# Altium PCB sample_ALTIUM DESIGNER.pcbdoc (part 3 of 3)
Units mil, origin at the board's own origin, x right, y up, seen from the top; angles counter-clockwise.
Board outline 2485.01 x 1905 mil, 6 copper layers (1 TallParts (2oz), 2 RTNS (2oz), 3 InternalPlane1 (2 oz), 4 InternalPlane2 (2 oz), 5 Signal (2oz), 6 LoParts (2oz)), stack 46.8 mil thick; 176 components, 89 nets, 769 pads, 0 vias.
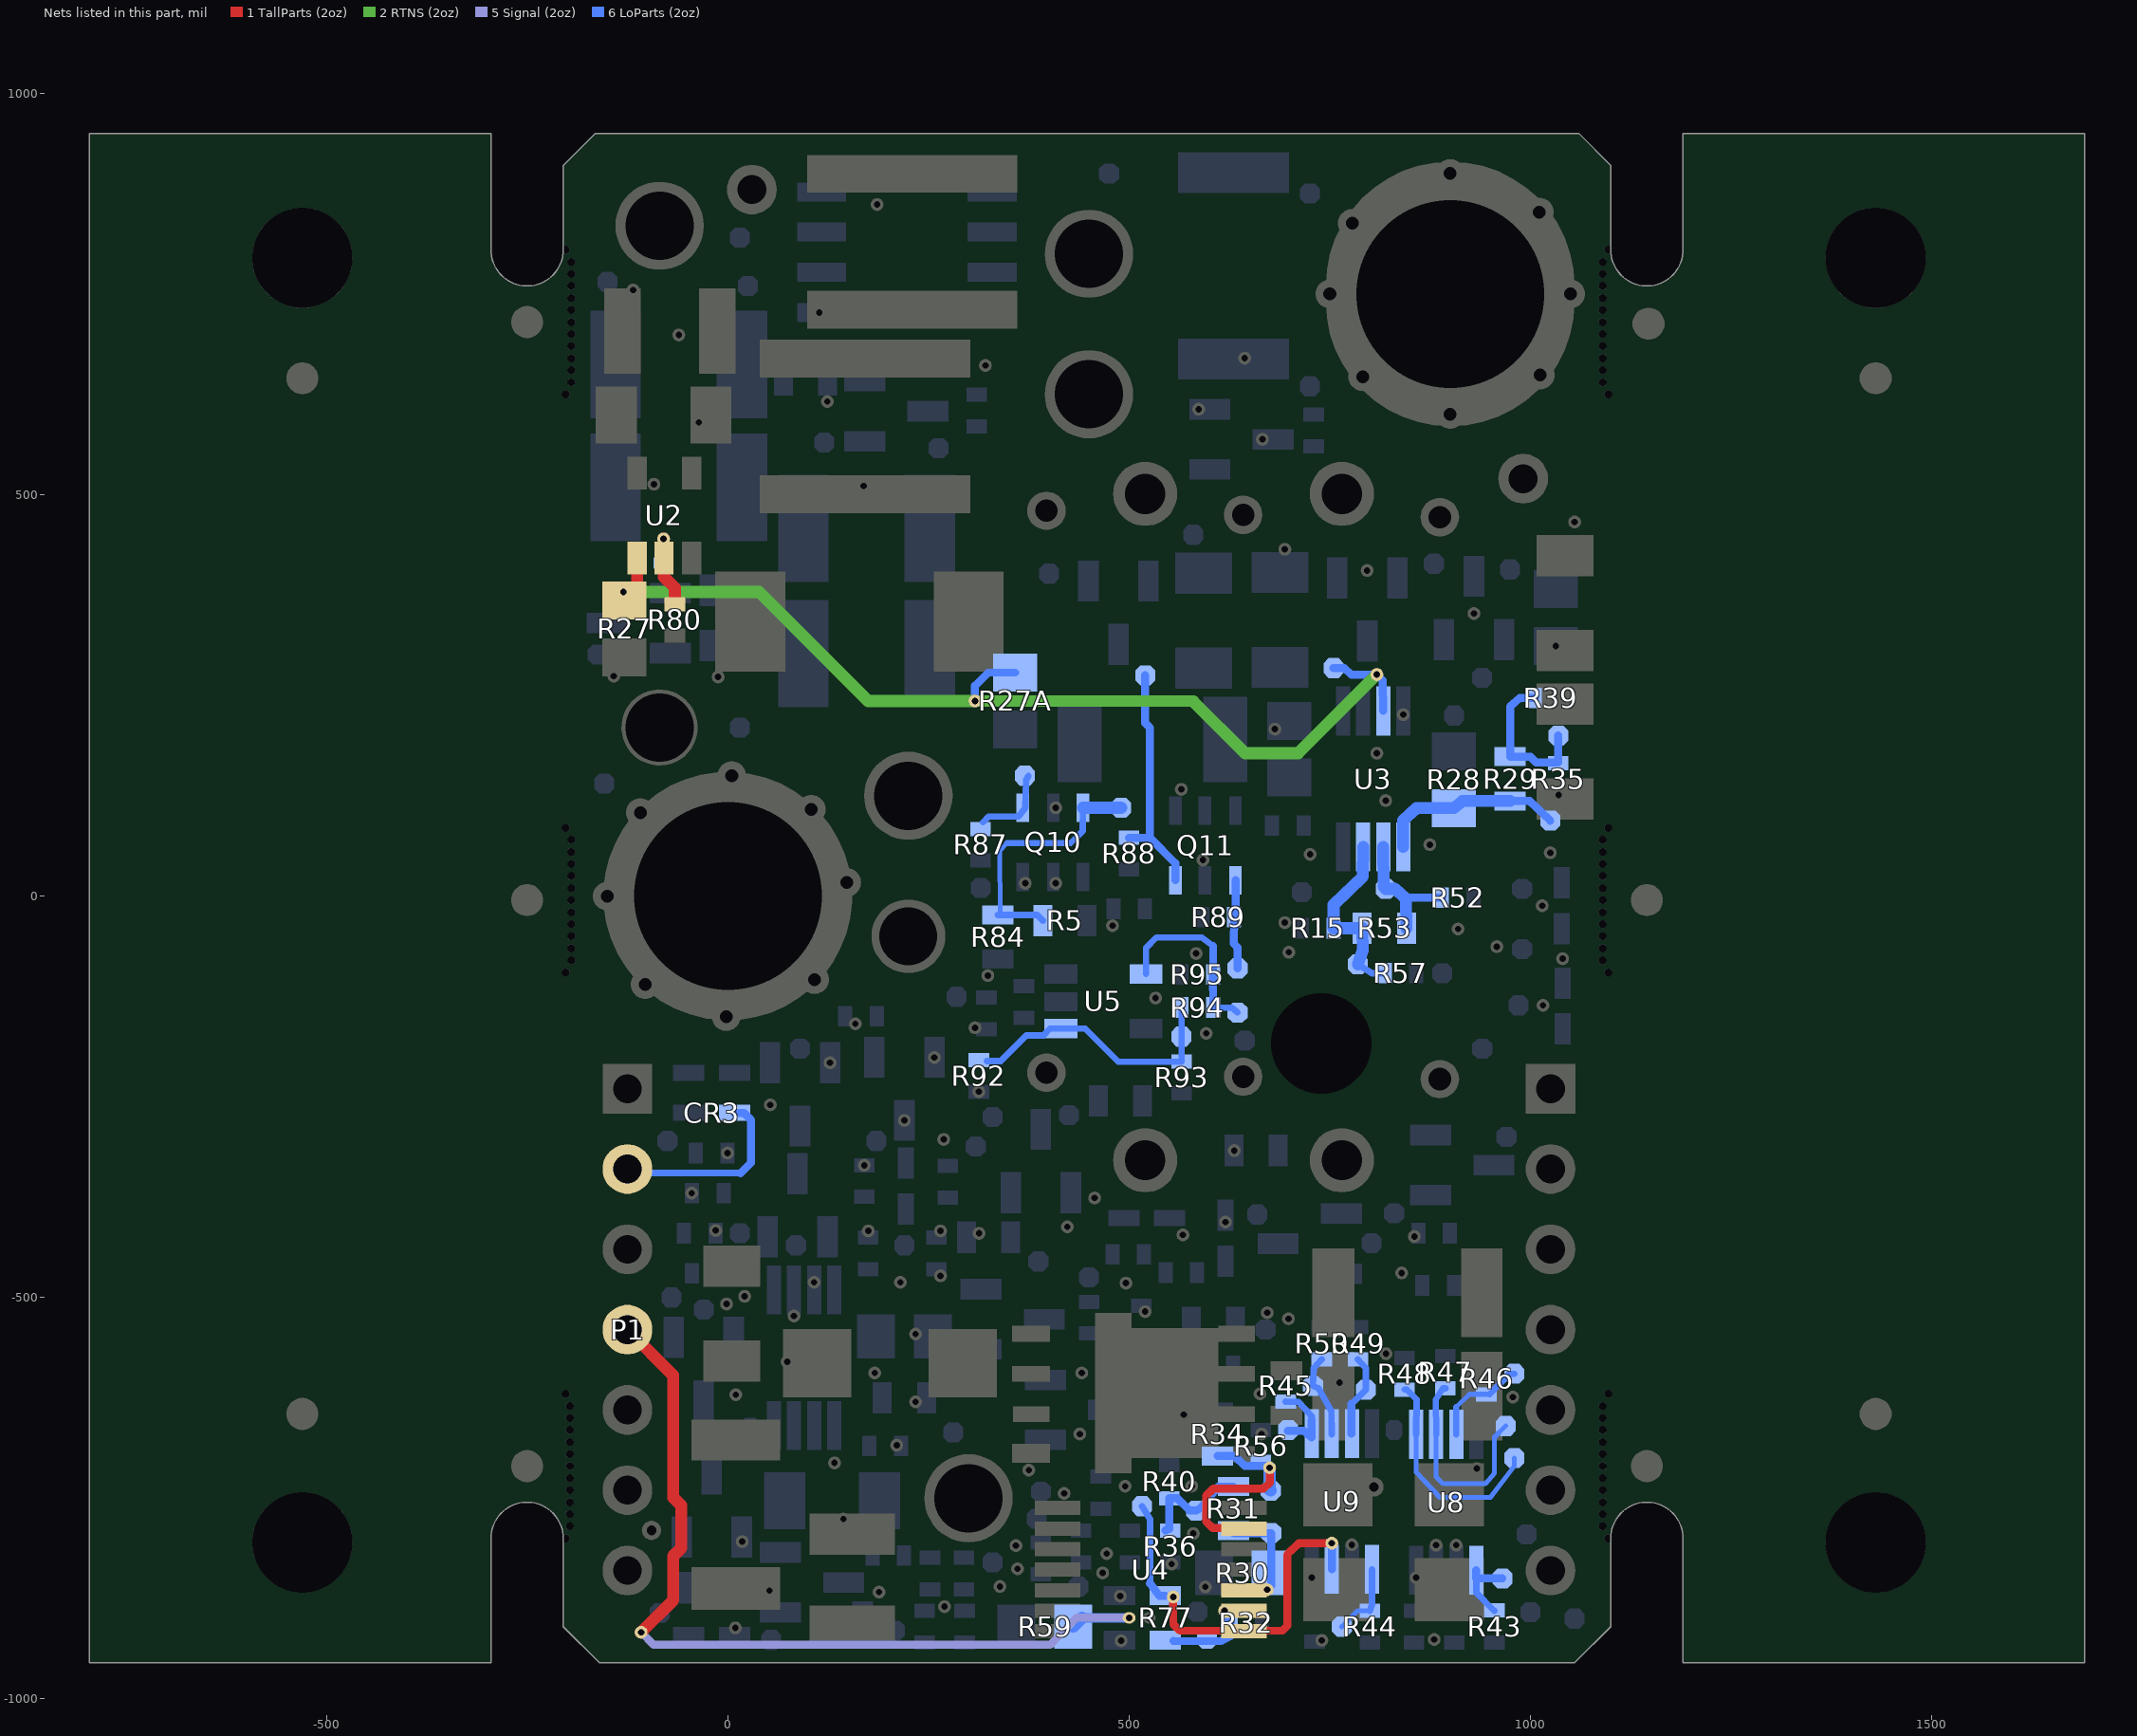
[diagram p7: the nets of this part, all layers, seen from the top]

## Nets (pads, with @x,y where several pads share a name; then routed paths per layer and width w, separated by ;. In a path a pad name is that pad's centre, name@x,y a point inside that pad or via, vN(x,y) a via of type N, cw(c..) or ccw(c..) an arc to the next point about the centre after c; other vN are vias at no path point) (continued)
NetQ10_4: pad.8@370,150 Q10.4 R87.2 | length 101.7
  6 LoParts (2oz) w8: R87.2@317.87,92 324.87,99 362,99 368.48,107.28 369.57,108.69 Q10.4@370.6,110 ; Q10.4@370.6,110.01 370.6,110.22 371.6,144 373.68,148.16 pad.8@374.6,150
NetQ10_6: pad.8@490,110 Q10.6 R5.1 R84.2 | length 332.3
  6 LoParts (2oz) w6: R84.2@339.5,-23.5 339.5,-23.44 339,57 348,66
  6 LoParts (2oz) w8: R84.2@336.54,-23.43 339.5,-23.44 385.5,-23.5 R5.1@392.45,-30.54 ; 348,66 427.1,66 442.1,81 442.5,110 Q10.6@442.5,110.31 Q10.6@445.6,110
  6 LoParts (2oz) w15: Q10.6@442.5,110 445.6,110 pad.8@490,110
NetQ11_4: pad.8@635,-90 Q11.4 R89.2 | length 111.7
  6 LoParts (2oz) w10: Q11.4@632.5,19.69 632.5,-17.5 R89.2@630.69,-26 630.5,-59.5 635,-64 pad.8@635,-90
NetQ11_6: pad.8@520,275 Q11.6 R88.2 | length 297.1
  6 LoParts (2oz) w10: R88.2@499.6,72.69 525.82,72.69 ; pad.8@520,275 520,215.5 525.82,209.69 525.82,72.69 ; Q11.6@557.5,19.69 557.5,41 525.82,72.69
NetR15_1: pad.8@785,-85 R15.1 R53.2 R57.1 U3.7 | length 235
  6 LoParts (2oz) w8: pad.8@785,-85 802.5,-96 R57.1@818.32,-96
  6 LoParts (2oz) w15: pad.8@785,-85 791,-68 R53.2@790.44,-40 R15.1@754.69,-40 754.69,-10.93 791.11,24.5 U3.7@791.5,61.35
NetR27_2: pad.2@308,243 pad.2@808.61,276 pad.2@-130,378.87 pad.8@754.61,284 R27.2 R27A.2 U2.1 U3.3 | length 1303.3
  1 TallParts (2oz) w15: pad.2@-130,378.87 -128.78,378.84 -113,378.5 U2.1@-113,421
  2 RTNS (2oz) w15: pad.2@-130,378.87 39,378.87 174.87,243 pad.2@308,243 308,243.24 580,242.5 644.5,178 710.61,178 pad.2@808.61,276
  6 LoParts (2oz) w10: pad.2@308,243 308,262 324.43,278.43 R27A.2@358,278.43 ; pad.8@754.61,284 768,284 777,276 pad.2@808.61,276 816.11,268.5 U3.3@816.5,230.65
NetR28_2: pad.8@1024.61,94 R28.2 R29.2 U3.5 | length 235.3
  6 LoParts (2oz) w10: R29.2@974.61,118.44 999,118.5 pad.8@1024.61,94
  6 LoParts (2oz) w15: U3.5@841.12,61.35 841.11,94.5 858,109.5 R28.2@904.33,109.56 915.5,118.5 R29.2@974.61,118.44
NetR29_1: pad.8@1034.61,200 R29.1 R35.1 R39.2 | length 193.6
  6 LoParts (2oz) w10: R39.2@1005.32,247 986.61,247 974.61,236 R29.1@974.61,173.56 1000,173.5 1007,166.5 1034.6,166.69 pad.8@1034.61,200
NetR30_2: pad.2@672.01,-864 pad.8@677,-793.5 R30.2 R31.2 U4.3 | length 136.4
  6 LoParts (2oz) w10: R31.2@629.28,-793 631,-793.5 pad.8@677,-793.5 677.01,-843 R30.2@677.01,-859 ; pad.2@672.01,-864 R30.2@677.01,-859 ; R30.2@676.43,-843 R30.2@677.01,-859
NetR31_1: pad.8@583.5,-765.5 R31.1 R36.1 R40.2 | length 150.9
  6 LoParts (2oz) w10: R36.1@545,-790.31 549.12,-788.41 549.94,-788.03 550,-788 R40.2@550.01,-750 550.01,-749.69 560,-750 574.51,-764.5 575.01,-765 pad.8@583.5,-765.5 pad.8@590,-761.5 ; pad.8@583.73,-765.15 pad.8@590,-761.5 ; R31.1@630,-735.44 611,-735.5 pad.8@590,-761.5
NetR32_2: pad.2@619,-890 pad.8@597,-925 R32.2 R77.1 U4.2 | length 133.5
  1 TallParts (2oz) w10: pad.2@619,-890 U4.2@643.12,-889.41
  6 LoParts (2oz) w6: pad.2@619,-890 pad.2@622.01,-890
  6 LoParts (2oz) w10: R77.1@555.01,-927.56 559,-928 597,-928 614,-928 626,-922 R32.2@626.32,-905 ; pad.2@619,-890 R32.2@626.24,-904.87 ; R32.2@626.24,-904.87 626.32,-904.87 R32.2@626.32,-905 ; R32.2@626.24,-904.87 R32.2@626.32,-905
NetR34_2: pad.2@675,-712 pad.8@676.5,-740.5 R34.2 R56.1 U4.6 | length 280.9
  1 TallParts (2oz) w10: U4.6@643.14,-787.05 604.06,-787.05 596.01,-779 596.01,-747 605.01,-738 667.51,-738 675,-731 pad.2@675,-712
  6 LoParts (2oz) w10: R34.2@610.01,-697.56 631,-697.5 644.01,-709.69 664,-709.69 R56.1@670.01,-709.69
  6 LoParts (2oz) w15: pad.2@675,-712 675,-739 pad.8@676.5,-740.5
NetR43_2: pad.8@965,-850 R43.2 U8.1 | length 92.5
  6 LoParts (2oz) w8: U8.1@932.5,-850 932.51,-867.81 954.61,-889.91 R43.2@955.01,-890.31
  6 LoParts (2oz) w10: U8.1@932.51,-839.65 932.5,-850 pad.8@965,-850
NetR44_2: pad.8@765.01,-910 R44.2 U9.1 | length 95.2
  6 LoParts (2oz) w6: pad.8@765.01,-910 784.7,-890.31 R44.2@800.01,-890.31
  6 LoParts (2oz) w8: R44.2@800.01,-890.31 802.51,-882.81 U9.1@802.5,-838.65
NetR45_1: pad.8@698,-665 R45.1 U9.5 | length 100.2
  6 LoParts (2oz) w8: R45.1@695.03,-629.87 R45.1@695.01,-629.69 711,-630 727.5,-648 U9.5@727.51,-652.19
  6 LoParts (2oz) w10: pad.8@697.5,-666 698,-666 717.5,-666 724.96,-672.34 727.5,-674.5 U9.5@727.5,-669.35 ; U9.5@727.5,-669.35 U9.5@727.51,-652.19
NetR46_1: pad.8@980,-595 R46.1 U8.7 | length 123.5
  6 LoParts (2oz) w6: 907.5,-636.5 924,-620.5 R46.1@944.95,-620.49 ; R46.1@945.01,-620.69 R46.1@949,-620.5
  6 LoParts (2oz) w8: U8.7@907.51,-670.35 907.5,-636.5 ; R46.1@949,-620.5 962,-607 974,-595 pad.8@980,-595
NetR47_1: pad.8@969,-660 R47.1 U8.6 | length 262.9
  6 LoParts (2oz) w6: U8.6@882.51,-670.35 882.5,-723 891,-732 944,-732 955,-719 955,-674 pad.8@969,-660
  6 LoParts (2oz) w8: U8.6@882.51,-670.35 882,-627 891,-613 R47.1@894,-613
NetR48_1: pad.8@980,-700 R48.1 U8.5 | length 275.8
  6 LoParts (2oz) w6: U8.5@857.51,-670.35 857.51,-717.5 887,-749 950,-749 980,-710 pad.8@980,-700
  6 LoParts (2oz) w8: R48.1@843,-614.69 846,-615 858,-627 U8.5@857.51,-670.35
NetR49_1: pad.8@795,-615 R49.1 U9.7 | length 113.8
  6 LoParts (2oz) w8: U9.7@777,-642 777,-632.5 pad.8@795,-615 795,-588 R49.1@785,-577
  6 LoParts (2oz) w10: U9.7@777,-669.85 777,-669.35 777.03,-669.23 777,-632.5
NetR50_1: pad.8@729,-610 R50.1 U9.6 | length 106.1
  6 LoParts (2oz) w8: R50.1@740,-577 730,-588 pad.8@729,-610 736,-613 752,-641 U9.6@752.5,-669.35 U9.6@752.51,-670.35
NetR52_2: pad.8@819.61,9 R52.2 R53.1 U3.6 | length 164
  6 LoParts (2oz) w10: 846,-2 R52.2@889.61,-2
  6 LoParts (2oz) w15: U3.6@816.5,61.35 817,12 819.72,9.5 pad.8@819.61,9 831,9 845,-3 R53.1@845.56,-40
NetR77_2: pad.2@555,-873 pad.2@752.5,-806 pad.8@516,-760 R77.2 U4.1 U9.3 | length 490.2
  1 TallParts (2oz) w10: pad.2@555,-873 555.01,-907 563.01,-915 643.14,-915 691.01,-915 697.01,-909 697.01,-820 711.5,-806 pad.2@752.5,-806
  6 LoParts (2oz) w8: pad.8@516,-760 526,-776 526,-856
  6 LoParts (2oz) w10: 526,-856 537.44,-871.44 R77.2@545,-871.44 ; U9.3@752.5,-838.65 pad.2@752.5,-806
NetR80_2: pad.2@-80,445 pad.8@-80,415 R80.2 U2.2 | length 116.9
  1 TallParts (2oz) w15: pad.2@-80,445 U2.2@-79.5,421 -79.5,397.5 -66,384 R80.2@-66,363.69
  6 LoParts (2oz) w10: pad.8@-80,415 pad.2@-80,445
NetR92_1: pad.8@565.27,-175 R92.1 R93.2 R94.2 U5.1 | length 343.9
  6 LoParts (2oz) w8: R92.1@322.73,-205.32 340.18,-205.32 372,-173.5 393,-173.5 401.5,-165 U5.1@415,-165 445,-165 486.31,-206.31 R93.2@565.27,-206.31 pad.8@565.27,-175 R94.2@565.31,-138.73
NetR94_1: pad.8@635,-145 R94.1 R95.1 U5.4 | length 234.1
  6 LoParts (2oz) w8: U5.4@521,-97 521,-65 534,-51.5 590.5,-51.5 604.68,-62.18 ; R94.1@604.68,-138.73 628,-139 pad.8@635,-145
  6 LoParts (2oz) w10: R95.1@604.18,-97.74 R94.1@604.68,-138.73 ; R95.1@604.68,-97.73 604.68,-62.18
PWM: CR3.2 P1.2 | length 238.7
  6 LoParts (2oz) w8: P1.2@-119.99,-345 16.01,-345
  6 LoParts (2oz) w10: P1.2@-124.99,-340 P1.2@-119.99,-345 ; CR3.2@8.51,-270 20.01,-270 29.01,-279 29.01,-332 16.01,-345
SLOWTRIPSET: P1.4 pad.2@500,-899 pad.2@-108,-917 R59.1 | length 1132.2
  1 TallParts (2oz) w15: P1.4@-124.99,-540 -68,-596.99 -68,-749 -58,-759 -58,-812 -68,-822 -68,-877 pad.2@-108,-917
  5 Signal (2oz) w10: pad.2@-108,-917 -92.5,-932.5 401.68,-932.5 434.01,-899 pad.2@500,-899 pad.2@502.01,-899
  6 LoParts (2oz) w12: R59.1@441.45,-899 pad.2@500,-899 pad.2@502.01,-899
  6 LoParts (2oz) w15: R59.1@430.45,-910 R59.1@441.45,-899
pads on no net: CR14.2 CR15.2 CR16.2 CR23.2 CR25.2 CR29.2 FD1.FD? FD2.FD? FD3.FD? FD4.FD5 FD5.FD? FD6.FD? FD7.FD? FD8.FD6 FD9.FD? FD10.FD? P3.1 P4.1 U10.1 U10.4 U10.6 U10.7

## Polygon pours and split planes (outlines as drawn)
28VA on 1 TallParts (2oz) (solid): 957.5,372.5 935,394.5 812,557 426,558 426,557 184,203 184.01,-53 225.01,-94 300.01,-94 326,-68 333,-59 644.5,-59.5 809,-59 958.5,234.5 957.01,200
28VOUTPUT on 1 TallParts (2oz) (solid): 1057.99,881 1026.99,912 383,911 382,854 383,685 338,685 337,578.5 337,563 361,534.5 431,535 503,576 1057,576.5
28VBUS on 1 TallParts (2oz) (solid): -11.95,164.71 -106.95,124.71 -143.95,124.71 -162.95,104.71 -162.95,-285.29 -110,-285 72.1,-469.14 115.1,-511.14 703.03,-510.54 798,-405 834.5,-372.5 836,-297 789.82,-238.43 644,-185 642,-133 485,-133 431.5,-100 277,-100.5 246,-122 209.5,-122 173,-103.5 158.5,-83 153.5,-56 155.05,-21.29 155.86,83.9 75.05,164.71 50.05,164.71
28VOUTPUT on 5 Signal (2oz) (solid): 968,521 1069,420 1069,-286 980,-286 905,-284 906,-179 904,495 924,515 972,515
28VOUTPUT on 3 InternalPlane1 (2 oz) (split plane): 1200.02,-799.96 ccw(c1145,-799.96) 1101.03,-766.9 1101.03,771.97 ccw(c1145,805.04) 1200.02,805.04 1200.02,939.99 1680,939.99 1679.99,-944.99 1200.02,-944.99
28VOUTPUT on 3 InternalPlane1 (2 oz) (split plane): 329.15,420.01 423.85,420.01 445.05,441.21 446.49,536.65 cw(c456.5,536.5) 449.42,543.58 473.92,568.08 cw(c481,561) 481,571.01 564,571.01 cw(c564,561) 571.26,567.9 590.26,547.9 cw(c583,541) 593.02,541 593.02,441.92 608.42,430.01 650.85,430.01 657.92,437.08 ccw(c665,430) 657.84,437 657.82,436.98 657.84,437 657.87,437.04 689.99,470.07 689.99,519.5 cw(c700,519.5) 692.96,526.63 732.96,566.13 cw(c740,559) 740,569.01 794,569.01 cw(c794,559) 800.88,566.27 800.86,566.29 800.88,566.27 834.84,534.31 cw(c828,527) 838.02,527 838.02,466.15 874.15,430.01 956.27,430.01 cw(c966.29,430) 960.02,437.81 1081,534.81 1081,711.67 cw(c900,750) 1046.92,637.55 cw(c1038.97,643.63) 1031.01,649.72 ccw(c900,750) 1064.99,750 ccw(c900,750) 1064.72,759.28 cw(c1074.72,759.85) 1081,767.65 1081,895.04 cw(c1091.02,895.04) 1089.99,905 1089.99,905.87 1055.88,939.99 389.19,939.99 cw(c380,936.01) 390.02,936.01 cw(c380,936.01) 387.12,928.97 300.02,840.88 300.02,449.15
no net on 3 InternalPlane1 (2 oz) (split plane): -181,154.91 ccw(c-191.01,155) -181,155 -181,895.46 ccw(c-191.01,895.46) -194.97,904.66 -194.97,905.85 -160.84,939.99 369.84,939.99 282.88,852.04 ccw(c290,845) 279.99,845 279.99,445 ccw(c290,445) 282.92,437.92 317.92,402.92 ccw(c325,410) 325,399.99 355.82,399.99 235.85,280.01 65,280.01 ccw(c65,270) 54.99,270 54.99,186.01 -23,186.01 ccw(c-23,176) -31.61,181.12 ccw(c1.97,-0.83) -102.74,151.71 ccw(c-97.07,143.45) -106.48,140.01
28VA on 3 InternalPlane1 (2 oz) (split plane): 186.92,-117.74 158.52,-110.22 158.52,-83.56 ccw(c-0.83,-1.97) 177.79,-13.92 182.04,-0.87 ccw(c179,6) 186.39,4.66 188.39,15.66 ccw(c181,17) 188.52,17 ccw(c181,17) 188.39,18.34 182.39,51.34 ccw(c175,50) 181.29,54.11 102.91,174.55 ccw(c93,176) 103.02,176 ccw(c93,176) 93,186.01 75.02,186.01 75.02,259.99 240,259.99 ccw(c240,270) 247.08,262.92 384.15,399.99 428,399.99 ccw(c428,410) 435.08,402.92 462.08,429.92 ccw(c455,437) 465.01,436.85 466.45,532.29 485.15,550.99 559.7,550.99 572.99,537 572.99,437 ccw(c583,437) 576.9,429.06 576.88,429.08 576.9,429.06 598.85,412.09 ccw(c605,420) 605,409.99 655,409.99 ccw(c655,420) 662.08,412.92 672.08,422.92 ccw(c665,430) 672.2,423.04 707.16,459 ccw(c700,466) 710.02,466 710.02,515.31 744.11,548.99 790.03,548.99 817.99,522.67 817.99,462 ccw(c828,462) 820.92,454.92 862.92,412.92 ccw(c870,420) 870,409.99 956.27,409.99 956.27,191.29 ccw(c966.29,191.29) 956.27,191.12 956.99,146.92 956.99,146.84 956.99,147 956.99,81.05 901.77,24.03 641.06,25.01 641.04,25.01 641.06,25.01 ccw(c641,15) 635.3,23.23 624.87,16.01 459,16.01 ccw(c459,6) 451.92,13.08 422.92,-15.92 ccw(c430,-23) 419.99,-23.08 419.99,-23.06 419.99,-23.08 420.54,-115.35 269.02,-114.99 ccw(c269,-125) 265.9,-115.48 222.9,-129.48 ccw(c226,-139) 222.16,-129.75 187.45,-117.89 ccw(c185,-125)
28VBUS on 3 InternalPlane1 (2 oz) (split plane): -181,-279.99 -95,-279.99 cw(c-95,-290) -87.92,-282.92 67.08,-437.92 cw(c60,-445) 70.02,-445 70.02,-465.85 104.15,-499.99 489.69,-499.99 514.02,-481.97 cw(c520,-490) 520,-479.99 710,-479.99 cw(c710,-490) 717.08,-482.92 739.15,-504.99 860.85,-504.99 889.99,-475.85 889.99,-298.07 830.08,-254.08 830.07,-254.07 830.08,-254.08 cw(c836,-246) 825.99,-246 825.99,-176.15 762.85,-113.01 620.15,-113.01 556.08,-177.08 cw(c549,-170) 549,-180.01 475,-180.01 cw(c475,-170) 467.9,-177.06 426.44,-135.39 270.58,-135.02 229.1,-148.52 cw(c226,-139) 217.31,-143.97 182.82,-132.2 149.08,-123.26 cw(c151,-116) 143.49,-116 143.49,-80 cw(c151,-80) 147.96,-73.13 170.13,-5.04 ccw(c-0.83,-1.97) 170.16,-1.97 ccw(c-0.83,-1.97) 156.91,64.01 90.55,165.99 69.36,165.99 cw(c65,175) 60.64,165.99 16.22,165.99 cw(c10.19,173.98) 9.72,163.98 ccw(c1.97,-0.83) -47.18,156.67 -93.54,130.63 cw(c-96,135) -96,129.99 -181,129.99 -181,36.17 cw(c0.83,1.97) -176.88,53.44 cw(c-167.26,50.66) -157.25,50.66 cw(c-167.26,50.66) -157.64,47.87 ccw(c0.83,1.97) -155.68,-50.23 cw(c-165.18,-53.39) -155.17,-53.39 cw(c-165.18,-53.39) -174.69,-56.56 cw(c0.83,1.97) -181,-32.23
no net on 3 InternalPlane1 (2 oz) (split plane): -155.84,-944.99 -183.86,-916.97 ccw(c-191.01,-909.96) -181,-909.96 -181,-300.01 -99.15,-300.01 49.99,-449.15 49.99,-470 ccw(c60,-470) 52.92,-477.08 92.92,-517.08 ccw(c100,-510) 100,-520.01 493,-520.01 ccw(c493,-510) 498.98,-518.03 523.31,-500.01 705.85,-500.01 727.92,-522.08 ccw(c735,-515) 735,-525.01 865,-525.01 ccw(c865,-515) 872.08,-522.08 907.08,-487.08 ccw(c900,-480) 910.02,-480 910.02,-293 ccw(c900,-293) 905.92,-284.92 905.93,-284.93 905.92,-284.92 846.02,-240.93 846.02,-172 ccw(c836,-172) 843.08,-164.92 774.08,-95.92 ccw(c767,-103) 767,-92.99 616,-92.99 ccw(c616,-103) 608.92,-95.92 544.85,-159.99 479.16,-159.99 440.61,-121.23 440.04,-27.12 463.15,-4.01 628,-4.01 ccw(c628,6) 633.7,-2.23 644.11,4.97 905.94,3.99 ccw(c906,14) 913.2,7.03 913.2,7.04 974.19,70.03 ccw(c967,77) 974.2,70.04 974.2,70.03 ccw(c967,77) 977.02,77 977.02,147 ccw(c967,147) 977.01,147.16 976.3,191.37 976.3,191.45 976.3,191.29 976.3,425.19 1081,509.13 1081,-909.96 ccw(c1091.02,-909.96) 1081.85,-914 1050.86,-944.99
28VOUTPUT on 3 InternalPlane1 (2 oz) (split plane): -784.98,-944.95 -784.98,939.99 -305.01,939.99 -305.01,805.04 ccw(c-250,805.04) -201.03,779.97 -201.03,155 cw(c-191.01,155) -201.03,155.09 -201.03,155.04 -205.01,-289.91 ccw(c-195,-290) -201.03,-298 -201.03,-774.89 ccw(c-250,-799.96) -305.01,-799.96 -305.01,-944.95
28VBUS on 4 InternalPlane2 (2 oz) (split plane): 1200.02,-799.96 ccw(c1145,-799.96) 1101.03,-766.9 1101.03,771.97 ccw(c1145,805.04) 1200.02,805.04 1200.02,939.99 1680,939.99 1679.99,-944.99 1200.02,-944.99
28VOUTPUT on 4 InternalPlane2 (2 oz) (split plane): 329.15,420.01 379.9,420.01 424.77,420.93 445.53,441.69 446.49,536.6 cw(c456.5,536.5) 449.42,543.58 473.92,568.08 cw(c481,561) 481,571.01 563,571.01 cw(c563,561) 570.08,568.08 590.08,548.08 cw(c583,541) 593.01,541.05 cw(c583,541) 593.02,541 593.01,541.05 593.49,441.46 608.4,430.01 650.85,430.01 657.82,436.98 689.06,470.06 689.99,519.17 cw(c700,519) 693.09,526.25 693.11,526.27 735.57,566.73 cw(c742.5,559.5) 742.69,569.51 742.71,569.51 795.67,568.51 cw(c795.5,558.5) 802.47,565.69 835.47,533.69 cw(c828.5,526.5) 838.52,526.5 cw(c828.5,526.5) 838.51,526.24 838.51,526.26 838.51,526.24 837.11,468.05 876.1,429.06 954.99,429.9 cw(c965,430) 958.79,437.86 1080.7,534.6 1080.7,710.27 cw(c900,750) 1046.92,637.55 cw(c1038.97,643.63) 1031.01,649.72 ccw(c900,750) 1064.99,750 ccw(c900,750) 1064.72,759.28 cw(c1074.72,759.85) 1080.7,767.88 1080.7,895.76 cw(c1090.71,895.76) 1089.99,905.75 1089.99,905.87 1055.88,939.99 389.19,939.99 cw(c380,936.01) 390.02,936.01 390.02,935 cw(c380,935) 387.08,927.92 300.02,840.85 300.02,449.15
no net on 4 InternalPlane2 (2 oz) (split plane): -181,136.1 -109.86,136.95 cw(c-100.66,140.92) -106.54,149.03 cw(c1.97,-0.83) 10.66,183.98 cw(c10.19,173.98) 18.18,180.01 54.99,180.01 54.99,270 cw(c65,270) 65,280.01 235.85,280.01 355.82,399.99 325,399.99 cw(c325,410) 317.92,402.92 282.92,437.92 cw(c290,445) 279.99,445 279.99,845 cw(c290,845) 282.92,852.08 370.79,939.96 cw(c380,936.01) 370.81,939.99 -160.84,939.99 -194.97,905.85 -194.97,904.24 cw(c-191.01,895.04) -181,895.04
28VA on 4 InternalPlane2 (2 oz) (split plane): 186.92,-117.74 158.52,-110.22 158.52,-83.56 ccw(c-0.83,-1.97) 177.89,-12.23 184.08,7.14 ccw(c181,14) 188.52,14 ccw(c181,14) 188.44,15.03 183.45,51.01 ccw(c176,50) 182.24,54.19 98.24,179.19 ccw(c92,175) 92,182.51 75.02,182.51 75.02,259.99 240,259.99 ccw(c240,270) 247.08,262.92 384.23,400.07 429.19,400.99 ccw(c429,411) 436.08,403.92 462.58,430.42 ccw(c455.5,437.5) 465.51,437.4 466.47,532.31 485.15,550.99 558.85,550.99 573,536.83 573.49,436.45 ccw(c583.5,436.5) 577.4,428.56 577.39,428.56 ccw(c583.5,436.5) 577.41,428.55 577.4,428.56 577.41,428.55 598.89,412.06 598.9,412.06 ccw(c605,420) 605,409.99 655,409.99 ccw(c655,420) 662.08,412.92 672.08,422.92 ccw(c665,430) 672.3,423.15 672.28,423.12 672.3,423.15 706.26,459.1 706.28,459.12 ccw(c699,466) 709.01,465.83 709.93,514.63 746.43,549.41 791.36,548.56 818.38,522.36 816.99,464.26 816.99,464.24 816.99,464.26 ccw(c827,464) 819.92,456.92 864.92,411.92 ccw(c872,419) 872.13,408.99 956.32,409.88 957.96,81.13 900.85,24.01 638,24.01 ccw(c638,14) 631.73,21.81 631.74,21.82 631.73,21.81 624.49,16.01 459,16.01 ccw(c459,6) 451.92,13.08 422.92,-15.92 ccw(c430,-23) 419.99,-23 419.99,-114.05 268.95,-114.99 268.94,-114.99 268.95,-114.99 ccw(c269,-125) 265.9,-115.48 222.9,-129.48 ccw(c226,-139) 222.16,-129.75 187.45,-117.89 187.43,-117.89 187.45,-117.89 ccw(c185,-125)
28VBUS on 4 InternalPlane2 (2 oz) (split plane): -181,-279.99 -95,-279.99 cw(c-95,-290) -87.92,-282.92 67.08,-437.92 cw(c60,-445) 70.02,-445 70.02,-465.85 104.15,-499.99 490.59,-499.99 513.89,-482.06 cw(c520,-490) 520,-479.99 710,-479.99 cw(c710,-490) 717.08,-482.92 739.15,-504.99 860.85,-504.99 889.99,-475.85 889.99,-298.07 830.08,-254.08 830.07,-254.07 830.08,-254.08 cw(c836,-246) 825.99,-246 825.99,-176.15 762.85,-113.01 620.1,-113.01 555.05,-177.11 555.03,-177.13 555.05,-177.11 cw(c548,-170) 547.86,-180.01 473.86,-179.01 cw(c474,-169) 466.84,-176 425.86,-134.09 371.17,-135.01 cw(c371,-125) 371,-135.01 280,-135.01 cw(c280,-125) 278.89,-134.95 270.62,-135.01 229.1,-148.52 cw(c226,-139) 217.31,-143.97 182.82,-132.2 149.08,-123.26 cw(c151,-116) 143.49,-116 143.49,-80 cw(c151,-80) 147.92,-73.14 170.15,-3.5 ccw(c-0.83,-1.97) 170.16,-1.97 ccw(c-0.83,-1.97) 155.84,66.53 88,167.49 71.62,167.49 cw(c65,175) 56.33,169.99 19.37,169.99 cw(c10.19,173.98) 9.72,163.98 ccw(c1.97,-0.83) -43.18,157.86 -101.68,127.55 cw(c-104,132) -101.7,127.54 -101.69,127.55 -101.68,127.55 -101.69,127.55 cw(c-104,132) -103.96,126.99 -103.94,126.99 -103.96,126.99 -181,126.07 -181,36.17 cw(c0.83,1.97) -176.88,53.44 cw(c-167.26,50.66) -157.25,50.66 cw(c-167.26,50.66) -157.64,47.87 ccw(c0.83,1.97) -155.88,-49.63 cw(c-165.39,-52.76) -155.38,-52.76 cw(c-165.39,-52.76) -174.91,-55.89 cw(c0.83,1.97) -181,-32.23
no net on 4 InternalPlane2 (2 oz) (split plane): -155.84,-944.99 -183.86,-916.97 ccw(c-191.01,-909.96) -181,-909.96 -181,-300.01 -99.15,-300.01 49.99,-449.15 49.99,-470 ccw(c60,-470) 52.92,-477.08 92.92,-517.08 ccw(c100,-510) 100,-520.01 494,-520.01 ccw(c494,-510) 500.11,-517.94 523.41,-500.01 705.85,-500.01 727.92,-522.08 ccw(c735,-515) 735,-525.01 865,-525.01 ccw(c865,-515) 872.08,-522.08 907.08,-487.08 ccw(c900,-480) 910.02,-480 910.02,-293 ccw(c900,-293) 905.92,-284.92 905.93,-284.93 905.92,-284.92 846.02,-240.93 846.02,-172 ccw(c836,-172) 843.08,-164.92 774.08,-95.92 ccw(c767,-103) 767,-92.99 616,-92.99 ccw(c616,-103) 608.95,-95.89 608.97,-95.87 608.95,-95.89 543.95,-159.93 478.27,-159.04 440.02,-119.92 440.02,-27.15 463.15,-4.01 628,-4.01 ccw(c628,6) 634.27,-1.81 641.51,3.99 905,3.99 ccw(c905,14) 912.08,6.92 975.08,69.92 ccw(c968,77) 978.02,77 ccw(c968,77) 978.01,77.05 976.3,420.03 976.3,420.05 cw(c966.29,420) 976.3,420 976.3,426.18 1080.7,509.03 1080.7,-601.32 ccw(c1090.01,-605) 1081,-609.37 1081,-909.96 ccw(c1091.02,-909.96) 1081.85,-914 1050.86,-944.99
28VOUTPUT on 1 TallParts (2oz) "U4 PADS vs U4 PADS" (split plane): -784.98,-944.95 -784.98,939.99 -305.01,939.99 -305.01,805.04 ccw(c-250,805.04) -201.03,779.97 -201.03,-774.89 ccw(c-250,-799.96) -305.01,-799.96 -305.01,-944.95

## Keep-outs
KeepOutLayer:
  lines w1: 1080,-903 1080.01,895 1041,935 1040.01,935 -144.99,935 -184.99,895 -184.99,-900 -145,-940 84.5,-940 134.5,-940 134,-940 1042,-940 1080,-902

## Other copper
1 TallParts (2oz):
  text ".Layer_Name" at 1115,-1050 h40
2 RTNS (2oz):
  text ".Layer_Name" at 1200,-1055 h40
5 Signal (2oz):
  text ".Layer_Name" at 1065,-1055 h40
6 LoParts (2oz):
  text "B1632-DP-006" at -170,-170 h25 r90
  text ".Layer_Name" at 1135,-1055 h40
3 InternalPlane1 (2 oz) (plane layer: these items are gaps in the copper):
  lines w8: 152.48,-86.36 ccw(c-0.83,-1.97) 156.08,75.53
  lines w10: -191.01,135 -96,135 -23,176 ; 151,-80 179,6
  lines w15: 93,176 175,50 181,17 179,6 ; 151,-80 151,-116 185,-125 226,-139
  lines w20: -191.01,-909.96 -191.01,895.46 ; -191.01,135 -191.01,155 -195,-290 -95,-290 -65,-320 0,-385 30,-415 60,-445 60,-470 100,-510 493,-510 520,-490 710,-490 735,-515 865,-515 900,-480 900,-293 836,-246 836,-172 ; -167.26,50.65 ccw(c0.83,1.97) -165.18,-53.39 ; -97.07,143.45 cw(c1.97,-0.83) 10.19,173.98 ; -68.74,-160.93 ccw(c-1.97,0.83) 52.76,-165.39 ; -23,176 93,176 ; 65,175 65,270 70,270 240,270 380,410 ; 226,-139 269,-125 430.62,-125.38 ; 380,936.01 290,845 290,445 325,410 380,410 ; 725.28,740.15 cw(c900,750) 761.03,856.37 ; 793.63,611.03 ccw(c900,750) 909.85,575.28 ; 836,-179 836,-172 ; 890.15,924.72 cw(c900,750) 1006.37,888.97 ; 1038.97,643.63 ccw(c900,750) 1074.72,759.85 ; 1091.02,-909.96 1091.02,895.04 ; 1091.02,530 966.29,430 ; -205,-799.96 ccw(c-250,-799.96) -295,-799.96 -295,-954.96 -795,-954.96 -795,950 -295,950 -295,805.04 ccw(c-250,805.04) -205,805.04 -204.99,805 -204.99,910 -164.99,950 1060.03,950 1100.01,910 ; -205,-799.96 -204.99,-799.96 ; -204.99,-799.96 -204.99,-910 -159.99,-955 1055.01,-955 1100.01,-910 1100.01,-799.96 ; 380,410 428,410 455,437 456.5,536.5 481,561 564,561 583,541 583,437 605,420 655,420 665,430 700,466 700,519.5 740,559 794,559 828,527 828,462 870,420 966.29,420 966.29,430 ; 430.62,-125.38 475,-170 549,-170 616,-103 767,-103 836,-172 ; 430.62,-125.38 430,-23 459,6 628,6 641,15 906,14 967,77 967,147 966.29,191.29 966.29,430 ; 1100,-799.96 cw(c1145,-799.96) 1190,-799.96 1190,-954.96 1190.01,-955 1690,-955 1690.01,950 1190,950 1190,805.04 cw(c1145,805.04) 1100,805.04 1100,910 ; 1100,-799.96 1100.01,-799.96 ; 1100,910 1100.01,910
  text ".Layer_Name" at 1050,-1050 h40
4 InternalPlane2 (2 oz) (plane layer: these items are gaps in the copper):
  lines w8: 152.48,-86.36 ccw(c-0.83,-1.97) 156.08,75.53
  lines w10: -188.01,131 -104,132 -21,175 65,175 ; 151,-80 181,14
  lines w15: 65,175 92,175 176,50 181,14 ; 151,-80 151,-116 185,-125 226,-139
  lines w20: -191.01,-909.96 -191.01,895.04 ; -191.01,-907 -191.01,891 ; -191.01,-290 -95,-290 0,-385 60,-445 60,-470 100,-510 494,-510 520,-490 710,-490 735,-515 865,-515 900,-480 900,-293 836,-246 836,-172 767,-103 616,-103 548,-170 474,-169 430,-124 ; -167.26,50.65 ccw(c0.83,1.97) -165.39,-52.76 ; -100.66,140.92 cw(c1.97,-0.83) 10.19,173.98 ; -68.74,-160.93 ccw(c-1.97,0.83) 52.76,-165.39 ; 65,175 65,270 240,270 380,410 ; 226,-139 269,-125 430,-124 ; 280,-125 371,-125 430,-124 ; 380,936.01 380,935 290,845 290,445 325,410 380,410 ; 725.28,740.15 cw(c900,750) 761.03,856.37 ; 793.63,611.03 ccw(c900,750) 909.85,575.28 ; 890.15,924.72 cw(c900,750) 1006.37,888.97 ; 966.29,430 966.29,420 ; 1038.97,643.63 ccw(c900,750) 1074.72,759.85 ; 1090.01,-605 1090.71,-604.3 1090.71,895.76 ; 1091.02,-909.96 1091.02,895.04 ; 1091.02,530 965,430 966.29,420 ; -205,-799.96 ccw(c-250,-799.96) -295,-799.96 -295,-954.96 -795,-954.96 -795,950 -295,950 -295,805.04 ccw(c-250,805.04) -205,805.04 -204.99,805 -204.99,910 -164.99,950 1060.03,950 1100.01,910 ; -205,-799.96 -204.99,-799.96 ; -204.99,-799.96 -204.99,-910 -159.99,-955 1055.01,-955 1100.01,-910 1100.01,-799.96 ; 380,410 429,411 455.5,437.5 456.5,536.5 481,561 563,561 583,541 583.5,436.5 605,420 655,420 665,430 699,466 700,519 742.5,559.5 795.5,558.5 828.5,526.5 827,464 872,419 966.29,420 ; 430,-124 430,-23 459,6 628,6 638,14 905,14 968,77 966.29,420 ; 1100,-799.96 cw(c1145,-799.96) 1190,-799.96 1190,-954.96 1190.01,-955 1690,-955 1690.01,950 1190,950 1190,805.04 cw(c1145,805.04) 1100,805.04 1100,910 ; 1100,-799.96 1100.01,-799.96 ; 1100,910 1100.01,910
  text ".Layer_Name" at 1075,-1050 h40

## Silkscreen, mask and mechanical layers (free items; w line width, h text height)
TopOverlay:
  text "A1632-DP-" at 85,-405 h40
  text ".Layer_Name" at 1225,-1050 h40
BottomOverlay:
  text ".Layer_Name" at 1150,-1050 h25
TopPaste:
  text ".Layer_Name" at 1230,-1060 h40
BottomPaste:
  text ".Layer_Name" at 1240,-1055 h40
TopSolder:
  rectangle: -165,-9 -102,123
  rectangle: -163,-186 140,-22
  lines w50: -116.76,109.39 ccw(c0,0) 126.52,-97.95 ; -0.99,150 cw(c0,0) 131.39,72.37 ; 897.43,590.02 cw(c900,750) 897.48,590.02 ccw(c900,750) 897.43,590.02
  text ".Layer_Name" at 1240,-1055 h40
BottomSolder:
  text ".Layer_Name" at 1240,-1055 h40
Mechanical1:
  circle w2: c739.5,-184 r62.5
  circle w2: c0,0 r117
  circle w2: c900,750 r117
  lines w2: -795,-955 -795,950 -294.99,950 -295,805 ; -795,-954.96 -295,-954.96 -295,-799.96 cw(c-250,-799.96) -205,-799.96 -204.99,-909.96 ; -545,-805 -515,-805 ; -545,-645 -515,-645 ; -545,645 -515,645 ; -545,795 -515,795 ; -530,-820 -530,-790 ; -530,-660 -530,-630 ; -530,630 -530,660 ; -530,780 -530,810 ; -295,625.04 cw(c-250,625.04) -205,625.04 ; -294.99,626 -295,85.04 ccw(c-250,85.04) -205,85.04 -204.99,626 ; -295,805.04 ccw(c-250,805.04) -205,805.04 ; -204.99,-910 -159.99,-955 1055.01,-955 1100.01,-910 ; -204.99,805 -204.99,910 -164.99,950 1060.01,950 1100.01,910 1100,805.04 ccw(c1145,805.04) 1190,805.04 ; -140,-840 -110,-840 ; -125,-855 -125,-825 ; -15,0.04 15,0.04 ; 0,-14.96 0,15.04 ; 725,-183.5 755,-183.5 ; 740,-198.5 740,-183.5 740,-168.5 ; 885,750 915,750 ; 900,734.96 900,764.96 ; 1010,-840 1040,-840 ; 1025,-855 1025,-825 ; 1100.01,-909.96 1100.01,-799.96 cw(c1145,-799.96) 1190,-799.96 1190,-954.96 ; 1100.01,625 1100,85.04 ccw(c1145,85.04) 1190,85.04 1190.01,626 ; 1100,625.04 cw(c1145,625.04) 1190,625.04 ; 1190.01,-955 1690.01,-955 1690.01,950 1190,950 1190,805 ; 1415,-805 1445,-805 ; 1415,-645 1445,-645 ; 1415,645 1445,645 ; 1415,795 1445,795 ; 1430,-820 1430,-790 ; 1430,-660 1430,-630 ; 1430,630 1430,660 ; 1430,780 1430,810 ; -295,-619.96 ccw(c-250,-619.96) -205,-619.96 -204.99,-94.96 ccw(c-250,-94.96) -295,-94.96 -295,-619.96 ; 1100,-619.96 ccw(c1145,-619.96) 1190,-619.96 1190,-94.96 ccw(c1145,-94.96) 1100,-94.96 1100,-619.96
Mechanical2:
  circle w1: c425,-273 r21
  lines w20: 164.5,418 421.5,418 457,453.5 457,482 457,547 482.5,572.5 561,572.5 582,551.5 582,442 613,411 665.5,411 699,444.5 699,548.5 723.5,573 808.5,573 830,551.5 830,439 860,409 953,409
  text "234+0.005\-0.000 (2X)" at -450,1045 h100
  text "OUT" at 1245,435 h100
  text "IN" at -515,-50 h100
Mechanical3:
  lines w1: -409.5,592 1152,592
  lines w2: -206.99,-956 1082.01,-955.99 ; -206.36,-956.62 -206.36,957.37 1082.64,957.38 1082.64,-956.61 ; 1082.64,562.64 1082.64,890 ; -249.86,-999.62 1125.14,-999.62 1125.14,1000.38 -249.86,1000.38 -249.86,-999.62
Mechanical4:
  lines w50: -825,-610 -825,-985 -455,-985 ; -825,610 -825,980 -450,980 ; 1345,-985 1720,-985 1720,-615 ; 1350,980 1720,980 1720,605
  text "AMETEK AEROSPACE" at 133,-1028.5 h40
  text ".Pcb_File_Name_No_Path" at 120,-1092 h40
  text ".Layer_Name" at 1225,-1110 h40
  text ".Print_Date" at 275,-1155 h40
Mechanical5:
  drawing of 175 lines, arcs and shapes, not listed
  text "J6" at 379.77,860.09 h25
  text "J4" at 79.77,820.09 h25
  text "J5" at 379.77,690.09 h25
  text "CR2" at 194.77,615.09 h25
  text "R5" at -25.23,490.09 h25
  text "C1" at 469.77,465.09 h25 r90
  text "CR1" at 224.77,370.09 h25
  text "J3" at 79.77,200.09 h25
  text "R1" at 509.77,175.09 h25
  text "J1" at 374.77,105.09 h25
  text "Q1" at 594.77,15.09 h25
  text "J2" at 379.77,-69.91 h25
  text "C2" at 519.77,-114.91 h25
  text "R2" at 484.77,-444.91 h25
  text "Q2" at 589.77,-449.91 h25
  text "B1632-FH-001" at 329.77,-604.91 h25 r270
  text "Q4" at 79.77,-664.91 h25
  text "R3" at 509.77,-679.91 h25
  text "J7" at 339.77,-894.91 h25
  text "Q3" at 594.77,-909.91 h25
  text "R4" at 74.77,-914.91 h25
Mechanical6:
  region: 337.08,891.52 337.08,816.52 373.08,816.52 373.08,891.52
  region: 447.73,816.94 447.73,891.94 411.73,891.94 411.73,816.94
  region: -27.93,-113.3 37.02,-150.8 55.02,-119.62 -9.93,-82.12
  rectangle: -46.4,305.39 4.79,376.26
  rectangle: -164.51,305.39 -113.32,376.26
  region: 80.57,367.56 80.57,418.74 9.71,418.74 9.71,367.56
  region: 80.57,249.45 80.57,300.63 9.71,300.63 9.71,249.45
  region: 164.98,417.44 121.67,417.44 121.67,256.02 164.98,256.02
  region: -35.02,417.44 -78.33,417.44 -78.33,256.02 -35.02,256.02
  lines w5: 355.69,838.59 373.69,869.77 438.64,832.27 ; 421,832.57 485.95,870.07 503.95,838.89 ; -200.23,-949.91 1094.77,-949.91 1094.77,430.09 617.77,430.09 cw(c617.77,493.09) 554.77,493.09 554.77,945.09 -200.23,945.09 -200.23,-949.91
DrillDrawing:
  text ".Legend" at 1790,-460 h40
  text ".Layer_Name" at 1240,-1055 h40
